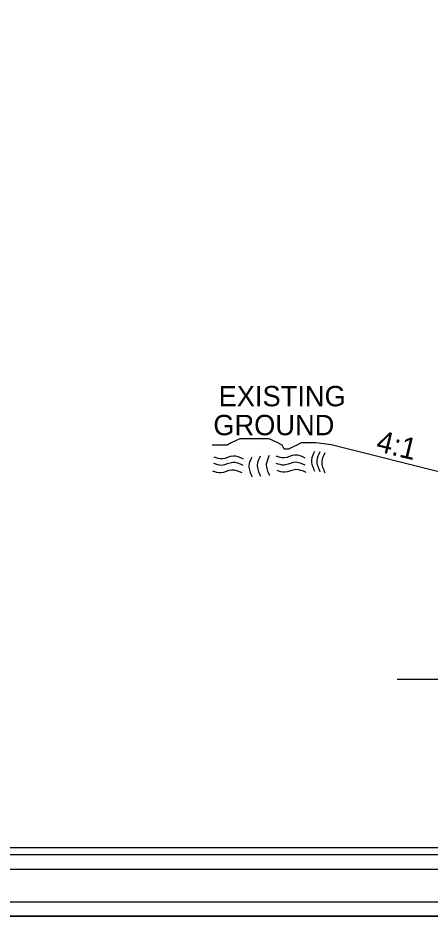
# Model space of a CAD drawing. Extents: x 2294455 to 2294795, y 719276 to 719941.
# Drawn here: x 2294501.1 to 2294531.2, y 719495.3 to 719560.8 of the extents above; entities that cross this region are included whole.
import ezdxf

# ---------------------------------------------------------------- set-up
doc = ezdxf.new("R2010")
doc.units = 0
for name, color, linetype in [('Default', 7, 'Continuous'), ('Old_Level_1', 7, 'Continuous'), ('Old_Level_11', 7, 'Continuous'), ('Old_Level_2', 7, 'Continuous'), ('Sheet Cutting Line CELL', 7, 'Continuous'), ('Sheet Plot Border Inside CELL', 7, 'Continuous'), ('Sheet Plot Border Outside CELL', 7, 'Continuous'), ('Sheet Typical CELL', 7, 'Continuous'), ('Typical Hinge Slope Arterial CELL', 7, 'Continuous')]:
    doc.layers.add(name, color=color, linetype=linetype)

msp = doc.modelspace()

# ---------------------------------------------------------------- linework, layer by layer
at = {"layer": 'Default'}
msp.add_lwpolyline([(2294454.524, 719715.329), (2294794.524, 719715.329), (2294794.524, 719495.329), (2294454.524, 719495.329)], close=True, dxfattribs=at)
at = {"layer": 'Old_Level_11'}
msp.add_line((2294590.775, 719512.584), (2294528.763, 719512.583), dxfattribs=at)
at = {"layer": 'Old_Level_2'}
for points in [[(2294517.547, 719528.644), (2294516.794, 719528.859), (2294516.002, 719528.656), (2294515.428, 719528.783)], [(2294517.547, 719528.644), (2294516.794, 719528.859), (2294516.002, 719528.656), (2294515.428, 719528.783)], [(2294518.169, 719528.787), (2294517.958, 719528.165), (2294518.186, 719527.344)], [(2294518.776, 719528.842), (2294518.564, 719528.22), (2294518.791, 719527.396)], [(2294519.432, 719528.892), (2294519.222, 719528.272), (2294519.446, 719527.449)], [(2294519.432, 719528.892), (2294519.222, 719528.272), (2294519.446, 719527.449)], [(2294522.06, 719528.715), (2294521.311, 719528.931), (2294520.513, 719528.729), (2294519.943, 719528.858)], [(2294522.06, 719528.715), (2294521.311, 719528.931), (2294520.513, 719528.729), (2294519.943, 719528.858)], [(2294522.725, 719529.2), (2294522.512, 719528.577), (2294522.74, 719527.756)], [(2294522.725, 719529.2), (2294522.512, 719528.577), (2294522.74, 719527.756)], [(2294523.114, 719529.159), (2294522.905, 719528.537), (2294523.133, 719527.712)], [(2294523.114, 719529.159), (2294522.905, 719528.537), (2294523.133, 719527.712)], [(2294523.479, 719529.087), (2294523.268, 719528.468), (2294523.496, 719527.644)], [(2294523.479, 719529.087), (2294523.268, 719528.468), (2294523.496, 719527.644)], [(2294517.527, 719528.172), (2294516.774, 719528.389), (2294515.982, 719528.184), (2294515.408, 719528.313)], [(2294517.527, 719528.172), (2294516.774, 719528.389), (2294515.982, 719528.184), (2294515.408, 719528.313)], [(2294522.065, 719528.192), (2294521.311, 719528.405), (2294520.52, 719528.202), (2294519.948, 719528.331)], [(2294522.065, 719528.192), (2294521.311, 719528.405), (2294520.52, 719528.202), (2294519.948, 719528.331)], [(2294517.451, 719527.627), (2294516.699, 719527.841), (2294515.904, 719527.638), (2294515.331, 719527.768)], [(2294517.451, 719527.627), (2294516.699, 719527.841), (2294515.904, 719527.638), (2294515.331, 719527.768)], [(2294522.123, 719527.664), (2294521.371, 719527.876), (2294520.573, 719527.678), (2294520.001, 719527.805)], [(2294522.123, 719527.664), (2294521.371, 719527.876), (2294520.573, 719527.678), (2294520.001, 719527.805)]]:
    msp.add_spline(points, degree=3, dxfattribs=at)
at = {"layer": 'Sheet Cutting Line CELL'}
msp.add_line((2294791.96, 719496.338), (2294455.16, 719496.338), dxfattribs=at)
at = {"layer": 'Sheet Plot Border Inside CELL'}
msp.add_lwpolyline([(2294790.424, 719710.839), (2294457.124, 719710.839), (2294457.124, 719499.819), (2294790.424, 719499.819)], close=True, dxfattribs=at)
at = {"layer": 'Sheet Plot Border Outside CELL'}
for points in [[(2294793.79, 719718.758), (2294456.99, 719718.758), (2294456.99, 719498.758), (2294793.79, 719498.758)], [(2294794.524, 719715.329), (2294454.524, 719715.329), (2294454.524, 719495.329), (2294794.524, 719495.329)]]:
    msp.add_lwpolyline(points, close=True, dxfattribs=at)
at = {"layer": 'Sheet Typical CELL'}
msp.add_lwpolyline([(2294787.924, 719710.329), (2294487.924, 719710.329), (2294487.924, 719500.329), (2294787.924, 719500.329)], close=True, dxfattribs=at)
at = {"layer": 'Typical Hinge Slope Arterial CELL'}
msp.add_line((2294533.953, 719527.177), (2294523.952, 719529.677), dxfattribs=at)
msp.add_lwpolyline([(2294523.952, 719529.677), (2294522.83, 719529.817), (2294522.522, 719529.817), (2294522.059, 719529.817), (2294521.751, 719529.817), (2294521.443, 719529.664), (2294521.135, 719529.509), (2294520.827, 719529.354), (2294520.52, 719529.354), (2294520.365, 719529.664), (2294520.057, 719529.817), (2294519.749, 719529.972), (2294519.441, 719530.125), (2294519.133, 719530.125), (2294518.825, 719530.125), (2294518.517, 719530.125), (2294518.209, 719530.125), (2294517.901, 719530.125), (2294517.593, 719530.125), (2294517.285, 719530.125), (2294516.977, 719529.972), (2294516.669, 719529.817), (2294516.361, 719529.664), (2294515.899, 719529.664), (2294515.591, 719529.664), (2294515.283, 719529.664)], dxfattribs=at)

# ---------------------------------------------------------------- texts
at = {"layer": 'Old_Level_1'}
for s, height, rotation, p in [('EXISTING', 1.4844, 0.00004, (2294515.746, 719532.489)), ('GROUND', 1.4844, 0.00004, (2294515.359, 719530.38)), ('4:1', 1.5625, 346.14338, (2294527.144, 719529.244))]:
    msp.add_text(s, height=height, rotation=rotation, dxfattribs=at).set_placement(p)

doc.saveas('drawing.dxf')
